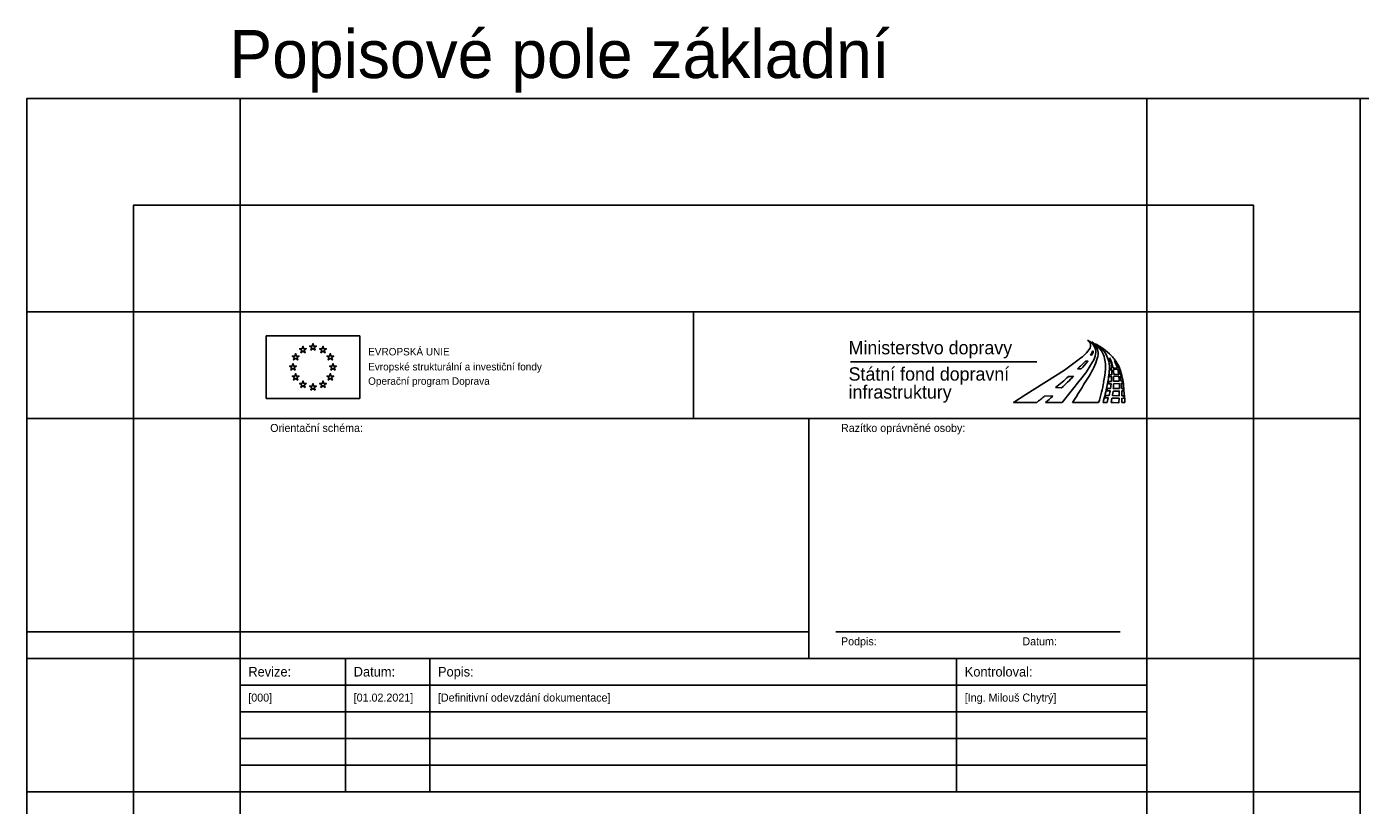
# Model space of a CAD drawing. Extents: x -27 to 48, y -2 to 33.
# Drawn here: x -2 to 23, y 18.45 to 33.05 of the extents above; entities that cross this region are included whole.
import ezdxf

# ---------------------------------------------------------------- set-up
doc = ezdxf.new("R2010")
doc.units = 0
for name, color, linetype in [('Default', 7, 'Continuous'), ('Rozpiska_Logo', 7, 'Continuous'), ('Rozpiska_pola_3', 7, 'Continuous'), ('Rozpiska_pole_1', 7, 'Continuous'), ('Rozpiska_pole_2', 7, 'Continuous'), ('Rozpiska_pole_4', 7, 'Continuous')]:
    doc.layers.add(name, color=color, linetype=linetype)

msp = doc.modelspace()

# ---------------------------------------------------------------- linework, layer by layer
at = {"layer": 'Default'}
for p, q in [((2, 27.7), (2, 31.7)), ((19, 27.7), (19, 31.7)), ((2, 27.7), (-2, 27.7)), ((10.5, 27.7), (10.5, 25.7)), ((19, 27.7), (23, 27.7)), ((-2, 25.7), (23, 25.7)), ((12.665, 21.2), (12.665, 25.7)), ((-2, 21.7), (12.665, 21.7)), ((-2, 21.2), (23, 21.2)), ((-2, 18.7), (23, 18.7))]:
    msp.add_line(p, q, dxfattribs=at)
for points in [[(-2, -2), (23, -2), (23, 31.7), (-2, 31.7)], [(23, -2), (48, -2), (48, 31.7), (23, 31.7)], [(0, 0), (21, 0), (21, 29.7), (0, 29.7)]]:
    msp.add_lwpolyline(points, close=True, dxfattribs=at)
at = {"layer": 'Rozpiska_Logo'}
msp.add_line((13.442, 26.762), (16.939, 26.762), dxfattribs=at)
for points in [[(2.49, 27.249), (4.243, 27.249), (4.244, 26.08), (2.49, 26.08), (2.49, 27.249)], [(3.116, 27.01), (3.164, 27.01), (3.179, 27.056), (3.194, 27.01), (3.242, 27.01), (3.203, 26.982), (3.218, 26.936), (3.179, 26.964), (3.14, 26.936), (3.155, 26.982), (3.116, 27.01)], [(3.155, 26.982), (3.14, 26.936), (3.179, 26.964), (3.218, 26.936), (3.203, 26.982), (3.242, 27.01), (3.194, 27.01), (3.179, 27.056), (3.164, 27.01), (3.116, 27.01), (3.155, 26.982)], [(3.304, 27.06), (3.352, 27.06), (3.367, 27.106), (3.382, 27.06), (3.43, 27.06), (3.391, 27.032), (3.406, 26.986), (3.367, 27.015), (3.328, 26.986), (3.343, 27.032), (3.304, 27.06)], [(3.343, 27.032), (3.328, 26.986), (3.367, 27.015), (3.406, 26.986), (3.391, 27.032), (3.43, 27.06), (3.382, 27.06), (3.367, 27.106), (3.352, 27.06), (3.304, 27.06), (3.343, 27.032)], [(3.491, 27.01), (3.54, 27.01), (3.554, 27.056), (3.569, 27.01), (3.618, 27.01), (3.579, 26.982), (3.593, 26.936), (3.554, 26.964), (3.515, 26.936), (3.53, 26.982), (3.491, 27.01)], [(3.53, 26.982), (3.515, 26.936), (3.554, 26.964), (3.593, 26.936), (3.579, 26.982), (3.618, 27.01), (3.569, 27.01), (3.554, 27.056), (3.54, 27.01), (3.491, 27.01), (3.53, 26.982)], [(2.979, 26.873), (3.027, 26.873), (3.042, 26.919), (3.057, 26.873), (3.105, 26.873), (3.066, 26.844), (3.081, 26.799), (3.042, 26.827), (3.003, 26.799), (3.018, 26.844), (2.979, 26.873)], [(3.018, 26.844), (3.003, 26.799), (3.042, 26.827), (3.081, 26.799), (3.066, 26.844), (3.105, 26.873), (3.057, 26.873), (3.042, 26.919), (3.027, 26.873), (2.979, 26.873), (3.018, 26.844)], [(3.629, 26.873), (3.677, 26.873), (3.692, 26.919), (3.707, 26.873), (3.755, 26.873), (3.716, 26.845), (3.731, 26.799), (3.692, 26.827), (3.653, 26.799), (3.668, 26.845), (3.629, 26.873)], [(3.668, 26.845), (3.653, 26.799), (3.692, 26.827), (3.731, 26.799), (3.716, 26.845), (3.755, 26.873), (3.707, 26.873), (3.692, 26.919), (3.677, 26.873), (3.629, 26.873), (3.668, 26.845)], [(16.931, 26), (16.501, 26), (16.732, 26.151), (17.452, 26.61), (17.732, 26.815)], [(17.892, 26.777), (17.892, 26.777), (17.847, 26.778)], [(17.942, 26.889), (17.962, 26.889)], [(17.993, 26.964), (17.993, 26.964), (17.977, 26.964)], [(2.928, 26.685), (2.977, 26.685), (2.992, 26.731), (3.006, 26.685), (3.055, 26.685), (3.016, 26.657), (3.031, 26.611), (2.992, 26.639), (2.953, 26.611), (2.967, 26.657), (2.928, 26.685)], [(2.967, 26.657), (2.953, 26.611), (2.992, 26.639), (3.031, 26.611), (3.016, 26.657), (3.055, 26.685), (3.006, 26.685), (2.992, 26.731), (2.977, 26.685), (2.928, 26.685), (2.967, 26.657)], [(2.979, 26.497), (3.027, 26.497), (3.042, 26.543), (3.057, 26.497), (3.105, 26.497), (3.066, 26.469), (3.081, 26.423), (3.042, 26.452), (3.003, 26.423), (3.018, 26.469), (2.979, 26.497)], [(3.018, 26.469), (3.003, 26.423), (3.042, 26.452), (3.081, 26.423), (3.066, 26.469), (3.105, 26.497), (3.057, 26.497), (3.042, 26.543), (3.027, 26.497), (2.979, 26.497), (3.018, 26.469)], [(3.629, 26.498), (3.677, 26.498), (3.692, 26.543), (3.707, 26.498), (3.755, 26.498), (3.716, 26.469), (3.731, 26.423), (3.692, 26.452), (3.653, 26.423), (3.668, 26.469), (3.629, 26.498)], [(3.668, 26.469), (3.653, 26.423), (3.692, 26.452), (3.731, 26.423), (3.716, 26.469), (3.755, 26.498), (3.707, 26.498), (3.692, 26.543), (3.677, 26.498), (3.629, 26.498), (3.668, 26.469)], [(3.679, 26.685), (3.727, 26.685), (3.742, 26.731), (3.757, 26.685), (3.805, 26.685), (3.766, 26.657), (3.781, 26.611), (3.742, 26.639), (3.703, 26.611), (3.718, 26.657), (3.679, 26.685)], [(3.718, 26.657), (3.703, 26.611), (3.742, 26.639), (3.781, 26.611), (3.766, 26.657), (3.805, 26.685), (3.757, 26.685), (3.742, 26.731), (3.727, 26.685), (3.679, 26.685), (3.718, 26.657)], [(17.698, 26.632), (17.764, 26.632)], [(18.341, 26.523), (18.301, 26.52), (18.296, 26.485), (18.339, 26.487)], [(18.342, 26.647), (18.309, 26.645), (18.308, 26.614), (18.341, 26.617)], [(18.444, 26.653), (18.364, 26.648)], [(18.452, 26.626), (18.371, 26.619)], [(18.379, 26.525), (18.47, 26.53)], [(18.471, 26.628), (18.484, 26.628), (18.474, 26.655), (18.459, 26.654)], [(18.5, 26.494), (18.518, 26.495), (18.51, 26.532), (18.493, 26.531)], [(3.116, 26.36), (3.164, 26.36), (3.179, 26.406), (3.194, 26.36), (3.242, 26.36), (3.203, 26.332), (3.218, 26.286), (3.179, 26.314), (3.14, 26.286), (3.155, 26.332), (3.116, 26.36)], [(3.155, 26.332), (3.14, 26.286), (3.179, 26.314), (3.218, 26.286), (3.203, 26.332), (3.242, 26.36), (3.194, 26.36), (3.179, 26.406), (3.164, 26.36), (3.116, 26.36), (3.155, 26.332)], [(3.304, 26.31), (3.352, 26.31), (3.367, 26.356), (3.382, 26.31), (3.43, 26.31), (3.391, 26.282), (3.406, 26.236), (3.367, 26.264), (3.328, 26.236), (3.343, 26.282), (3.304, 26.31)], [(3.343, 26.282), (3.328, 26.236), (3.367, 26.264), (3.406, 26.236), (3.391, 26.282), (3.43, 26.31), (3.382, 26.31), (3.367, 26.356), (3.352, 26.31), (3.304, 26.31), (3.343, 26.282)], [(3.491, 26.36), (3.54, 26.36), (3.555, 26.406), (3.569, 26.36), (3.618, 26.36), (3.579, 26.332), (3.594, 26.286), (3.555, 26.314), (3.516, 26.286), (3.53, 26.332), (3.491, 26.36)], [(3.53, 26.332), (3.516, 26.286), (3.555, 26.314), (3.594, 26.286), (3.579, 26.332), (3.618, 26.36), (3.569, 26.36), (3.555, 26.406), (3.54, 26.36), (3.491, 26.36), (3.53, 26.332)], [(17.749, 26.424), (17.408, 26), (17.101, 26)], [(17.286, 26.282), (17.4, 26.276)], [(17.624, 26.491), (17.624, 26.491), (17.531, 26.491)], [(18.333, 26.398), (18.283, 26.396), (18.277, 26.353), (18.328, 26.354), (18.316, 26.263), (18.261, 26.263), (18.25, 26.222), (18.308, 26.221), (18.29, 26.135), (18.225, 26.136), (18.218, 26.089), (18.275, 26.088), (18.255, 26)], [(18.369, 26.263), (18.484, 26.263)], [(18.484, 26.356), (18.372, 26.354)], [(18.375, 26.4), (18.479, 26.404)], [(18.474, 26.493), (18.376, 26.489)], [(18.518, 26.357), (18.543, 26.357), (18.536, 26.406), (18.511, 26.405)], [(18.527, 26.218), (18.56, 26.218), (18.554, 26.263), (18.524, 26.263)], [(17.235, 26.121), (17.235, 26.121), (17.088, 26.126)], [(18.365, 26.217), (18.355, 26.133), (18.48, 26.13), (18.482, 26.216), (18.365, 26.217)], [(18.532, 26), (18.531, 26.081), (18.571, 26.08), (18.566, 26.128), (18.53, 26.129)], [(18.093, 26), (17.605, 26)], [(18.177, 26), (18.255, 26)], [(18.327, 26), (18.373, 26)], [(18.532, 26), (18.588, 26)]]:
    msp.add_lwpolyline(points, dxfattribs=at)
msp.add_lwpolyline([(18.327, 26), (18.344, 26.083), (18.478, 26.083), (18.475, 25.999)], close=True, dxfattribs=at)
for centre, radius, start, end in [((17.273, 27.467), 0.797, 305.1305, 325.9532), ((17.829, 27.072), 0.116, 333.7821, 60.3253), ((17.764, 26.911), 0.289, 35.1291, 64.7751), ((17.659, 26.616), 0.605, 44.354, 59.6129), ((17.79, 26.894), 0.299, 8.8325, 54.3171), ((17.818, 26.949), 0.223, 358.3059, 35.1291), ((8.176, 14.325), 16.135, 51.8348, 52.3632), ((17.574, 26.192), 1.018, 55.8173, 63.4675), ((17.773, 26.731), 0.443, 21.6804, 44.0388), ((17.708, 26.309), 0.847, 45.7577, 58.8317), ((17.852, 26.684), 0.44, 29.5083, 48.0349), ((16.028, 28.492), 2.499, 311.9225, 316.7053), ((15.693, 28.076), 2.637, 321.2414, 331.1155), ((14.243, 29.883), 4.793, 317.2846, 319.5966), ((16.559, 27.344), 1.598, 326.3997, 339.6645), ((17.823, 26.991), 0.156, 319.6022, 350.325), ((17.829, 26.988), 0.166, 323.7342, 351.8118), ((17.729, 26.952), 0.312, 331.1155, 358.3059), ((17.627, 26.948), 0.459, 339.6691, 359.0927), ((17.628, 26.682), 0.596, 354.8309, 20.9259), ((17.86, 26.684), 0.433, 12.5999, 30.087), ((17.828, 26.659), 0.47, 350.7277, 14.6627), ((17.927, 26.594), 0.441, 6.9884, 33.3949), ((17.771, 26.608), 0.572, 3.8889, 23.6112), ((17.712, 26.301), 0.85, 32.4145, 46.3283), ((17.949, 26.477), 0.539, 19.1508, 35.05), ((17.292, 26.274), 1.213, 18.2045, 25.0006), ((17.901, 26.403), 0.636, 13.4543, 33.7828), ((16.549, 26.736), 1.676, 348.0644, 356.2998), ((16.258, 26.744), 2.04, 348.131, 355.4957), ((17.178, 26.567), 1.164, 357.822, 2.4688), ((17.422, 26.493), 0.957, 1.9262, 7.6145), ((17.662, 26.427), 0.815, 7.2316, 14.102), ((17.89, 26.443), 0.61, 8.3249, 17.6578), ((16.946, 26.146), 1.625, 2.7985, 14.4251), ((12.238, 32.429), 7.955, 309.3914, 311.7102), ((13.573, 30.473), 5.68, 312.3671, 315.4937), ((-22.272, 51.084), 47.111, 327.8282, 328.4861), ((15.385, 26.874), 2.846, 342.1151, 350.2059), ((15.032, 26.929), 3.279, 343.5415, 349.3721), ((20.202, 26.321), 1.871, 174.904, 177.6286), ((17.831, 26.33), 0.541, 352.9784, 2.6252), ((13.148, 26.5), 5.228, 358.9091, 359.8809), ((16.537, 26.337), 1.943, 1.988, 4.6084), ((17.853, 26.314), 0.633, 355.4573, 3.8566), ((18.122, 26.405), 0.388, 0.0904, 13.2769), ((17.454, 26.238), 1.071, 1.3852, 6.3824), ((19.107, 23.462), 3.342, 127.1682, 130.6153), ((18.951, 24.106), 2.647, 130.4231, 134.3309), ((14.589, 26.048), 3.942, 1.1818, 2.4809), ((15.29, 25.842), 3.301, 2.7322, 6.6695)]:
    msp.add_arc(centre, radius, start, end, dxfattribs=at)
at = {"layer": 'Rozpiska_pola_3'}
msp.add_line((13.165, 21.7), (18.5, 21.7), dxfattribs=at)
at = {"layer": 'Rozpiska_pole_1'}
msp.add_lwpolyline([(2, 27.7), (19, 27.7), (19, 1.7), (2, 1.7)], close=True, dxfattribs=at)
at = {"layer": 'Rozpiska_pole_2'}
msp.add_lwpolyline([(2, 25.7), (12.665, 25.7), (12.665, 21.7), (2, 21.7)], close=True, dxfattribs=at)
at = {"layer": 'Rozpiska_pole_4'}
for p, q in [((3.975, 18.7), (3.975, 21.2)), ((5.555, 18.7), (5.555, 21.2)), ((15.43, 18.7), (15.43, 21.2)), ((2, 20.7), (19, 20.7)), ((2, 20.2), (19, 20.2)), ((2, 19.7), (19, 19.7)), ((2, 19.2), (19, 19.2))]:
    msp.add_line(p, q, dxfattribs=at)
msp.add_lwpolyline([(2, 21.2), (19, 21.2), (19, 18.7), (2, 18.7)], close=True, dxfattribs=at)

# ---------------------------------------------------------------- texts
at = {"layer": 'Default'}
msp.add_text('Popisové pole základní', height=0.9, dxfattribs=at).set_placement((1.799, 32.085))
at = {"layer": 'Rozpiska_Logo'}
for s, height, p in [('EVROPSKÁ UNIE', 0.14, (4.401, 26.885)), ('Ministerstvo dopravy', 0.25, (13.407, 26.905)), ('Evropské strukturální a investiční fondy', 0.14, (4.401, 26.603)), ('Státní fond dopravní', 0.25, (13.407, 26.412)), ('Operační program Doprava', 0.14, (4.401, 26.334)), ('infrastruktury', 0.25, (13.407, 26.075))]:
    msp.add_text(s, height=height, rotation=0.0062, dxfattribs=at).set_placement(p)
at = {"layer": 'Rozpiska_pola_3'}
for s, p in [('Razítko oprávněné osoby:', (13.265, 25.45)), ('Podpis:', (13.265, 21.45)), ('Datum:', (16.665, 21.45))]:
    msp.add_text(s, height=0.15, dxfattribs=at).set_placement(p)
at = {"layer": 'Rozpiska_pole_2'}
msp.add_text('Orientační schéma:', height=0.15, dxfattribs=at).set_placement((2.565, 25.45))
at = {"layer": 'Rozpiska_pole_4'}
for s, height, p in [('Revize:', 0.18, (2.155, 20.865)), ('Datum:', 0.18, (4.13, 20.865)), ('Popis:', 0.18, (5.71, 20.865)), ('Kontroloval:', 0.18, (15.585, 20.865)), ('[000]', 0.15, (2.155, 20.395)), ('[01.02.2021]', 0.15, (4.13, 20.395)), ('[Definitivní odevzdání dokumentace]', 0.15, (5.71, 20.395)), ('[Ing. Milouš Chytrý]', 0.15, (15.585, 20.395))]:
    msp.add_text(s, height=height, dxfattribs=at).set_placement(p)

doc.saveas('drawing.dxf')
